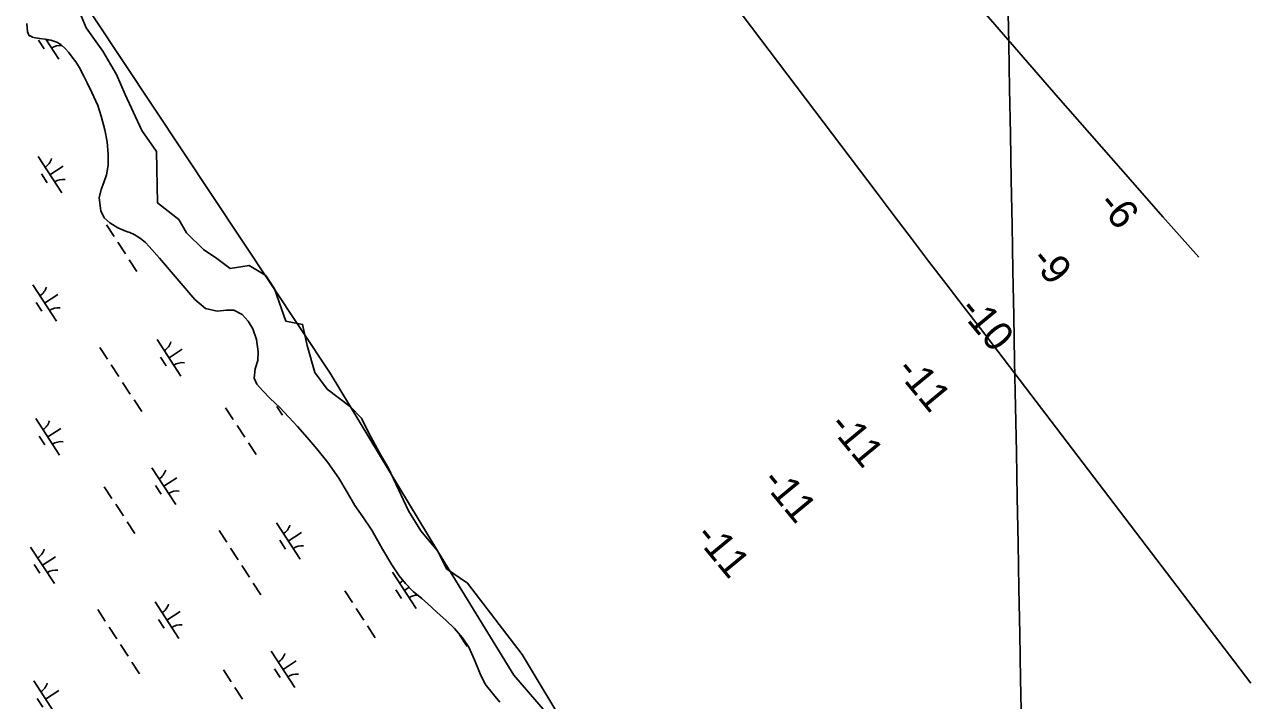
# Model space of a CAD drawing. Extents: x 3953924 to 3974542, y 193747 to 216192.
# Drawn here: x 3966813 to 3968214, y 199028 to 199804 of the extents above; entities that cross this region are included whole.
import ezdxf

# ---------------------------------------------------------------- set-up
doc = ezdxf.new("R2010")
doc.units = 0
for name, color, linetype in [('V-GRID-MAJR', 7, 'Continuous'), ('V-RIVR-EDGE', 7, 'Continuous'), ('V-RIVR-JETY', 7, 'Continuous'), ('V-RIVR-RANG', 7, 'Continuous'), ('V-TOPO-MINR', 7, 'Continuous'), ('V-WETL-SWMP', 7, 'Continuous')]:
    doc.layers.add(name, color=color, linetype=linetype)

msp = doc.modelspace()

# ---------------------------------------------------------------- linework, layer by layer
at = {"layer": 'V-GRID-MAJR'}
msp.add_spline([(3967994.9, 197070.8), (3967932.3, 200408.2), (3967818.6, 206468.2), (3967751, 210066.7)], degree=3, dxfattribs=at)
at = {"layer": 'V-RIVR-EDGE'}
msp.add_lwpolyline([(3966869.1, 199837.6), (3966884.5, 199800.5), (3966903.7, 199773.6), (3966919.1, 199746.7), (3966929.3, 199723.7), (3966948.5, 199682.7), (3966965.2, 199658.4), (3966966.5, 199599.4), (3966990.8, 199580.2), (3966999.8, 199564.9), (3967019, 199545.7), (3967034.3, 199535.4), (3967049.7, 199523.9), (3967071.5, 199527.7), (3967090.7, 199516.2), (3967100.9, 199500.8), (3967113.7, 199463.7), (3967132.9, 199459.9), (3967138.1, 199435.5), (3967147, 199404.8), (3967161.1, 199385.6), (3967188, 199365.1), (3967200.8, 199352.3), (3967208.5, 199335.6), (3967221.3, 199312.6), (3967231.5, 199294.7), (3967254.6, 199246), (3967268.7, 199222.9), (3967287.9, 199199.9), (3967298.1, 199179.4), (3967322.5, 199162.7), (3967385.2, 199080.8), (3967437.7, 198993.7)], dxfattribs=at)
at = {"layer": 'V-RIVR-JETY'}
msp.add_lwpolyline([(3965387.4, 201766), (3965676.4, 201395.8), (3965795.6, 201267.6), (3965922, 201152), (3966044.8, 201002.1), (3966216.4, 200738.4), (3966283.2, 200639.1), (3966436.7, 200467.6), (3966530.6, 200361), (3966624.5, 200225.5), (3966685.9, 200111.8), (3966696.8, 200091.9), (3966718.4, 200064.8), (3966859.3, 199862.5), (3966893.6, 199812), (3967164.5, 199403.8), (3967289.1, 199197.9), (3967375.8, 199057.1), (3967522.1, 198887.3), (3967612.4, 198786.2), (3967746, 198636.3), (3967827.3, 198542.4), (3968004.3, 198338.3), (3968150.6, 198174)], dxfattribs=at)
at = {"layer": 'V-TOPO-MINR'}
for points in [[(3968162.6, 199537.2), (3968121.1, 199583.5), (3968086.5, 199622.8), (3968000.8, 199720.6), (3967915.6, 199818.9), (3967831, 199917.8), (3967746.9, 200017.1), (3967610.1, 200179.9), (3967594.8, 200198.2), (3967579.6, 200216.4), (3967564.4, 200234.8), (3967549.3, 200253.1), (3967127.4, 200767.1)], [(3968222.1, 199047.8), (3967951.2, 199403.4), (3967931.4, 199429.3), (3967911.6, 199455.1), (3967891.8, 199481), (3967872, 199506.8), (3967852.1, 199532.6), (3967832.3, 199558.5), (3967812.6, 199584.4), (3967792.9, 199610.4), (3967452.8, 200059.9)]]:
    msp.add_lwpolyline(points, dxfattribs=at)
at = {"layer": 'V-WETL-SWMP'}
for p, q in [((3966816.3, 199805.2), (3966816.9, 199795.9)), ((3966816.9, 199795.9), (3966819.1, 199791.2)), ((3966819.1, 199791.2), (3966819.9, 199791.2)), ((3966819.9, 199791.2), (3966822.6, 199789.6)), ((3966822.6, 199789.6), (3966826.1, 199789.1)), ((3966826.1, 199789.1), (3966830.7, 199788.3)), ((3966829.5, 199786.3), (3966836, 199776.2)), ((3966830.7, 199788.3), (3966837.3, 199787.4)), ((3966837.3, 199787.4), (3966843.9, 199786.1)), ((3966838.1, 199787.2), (3966852.9, 199764.5)), ((3966839.2, 199785.5), (3966841, 199786.6)), ((3966843.9, 199786.1), (3966850.5, 199784)), ((3966850.5, 199784), (3966855.1, 199781.2)), ((3966855.1, 199781.2), (3966860.8, 199776.4)), ((3966860.8, 199776.4), (3966864.2, 199772.4)), ((3966864.2, 199772.4), (3966868.4, 199766.9)), ((3966868.4, 199766.9), (3966872.6, 199761.4)), ((3966872.6, 199761.4), (3966876.3, 199755.1)), ((3966876.3, 199755.1), (3966881.6, 199744.9)), ((3966881.6, 199744.9), (3966885.7, 199737.1)), ((3966885.7, 199737.1), (3966890.9, 199726.1)), ((3966890.9, 199726.1), (3966897.6, 199711.2)), ((3966897.6, 199711.2), (3966901.7, 199699)), ((3966901.7, 199699), (3966906, 199683.4)), ((3966906, 199683.4), (3966908.5, 199669.4)), ((3966908.5, 199669.4), (3966909.8, 199655)), ((3966909.8, 199655), (3966909.5, 199642.9)), ((3966829.1, 199652.7), (3966856.3, 199610.8)), ((3966842.7, 199631.8), (3966857.8, 199641.6)), ((3966909.5, 199642.9), (3966907.8, 199631.7)), ((3966833, 199632.6), (3966839.5, 199622.5)), ((3966907.8, 199631.7), (3966904.5, 199622.8)), ((3966901.6, 199614.7), (3966899.5, 199605.4)), ((3966904.5, 199622.8), (3966901.6, 199614.7)), ((3966899.5, 199605.4), (3966901.1, 199590.2)), ((3966901.1, 199590.2), (3966904.9, 199582.4)), ((3966904.9, 199582.4), (3966911.4, 199576.4)), ((3966907.7, 199574.4), (3966916.5, 199561)), ((3966911.4, 199576.4), (3966920.6, 199570.8)), ((3966920.6, 199570.8), (3966930.6, 199566.7)), ((3966930.6, 199566.7), (3966934.5, 199565.5)), ((3966934.5, 199565.5), (3966939.5, 199563.1)), ((3966939.5, 199563.1), (3966946.8, 199558.6)), ((3966946.8, 199558.6), (3966952.5, 199553.9)), ((3966920.8, 199554.3), (3966929.5, 199540.9)), ((3966952.5, 199553.9), (3966956.7, 199549.5)), ((3966956.7, 199549.5), (3966968.5, 199536.1)), ((3966933.9, 199534.2), (3966942.6, 199520.8)), ((3966968.5, 199536.1), (3967009.1, 199488.6)), ((3966823.1, 199505.4), (3966850.4, 199463.5)), ((3966836.7, 199484.4), (3966851.8, 199494.2)), ((3967009.1, 199488.6), (3967021.4, 199478.3)), ((3966827, 199485.2), (3966833.5, 199475.2)), ((3967021.4, 199478.3), (3967034.9, 199474.9)), ((3967034.9, 199474.9), (3967045.4, 199476.3)), ((3967045.4, 199476.3), (3967054, 199476.1)), ((3967054, 199476.1), (3967063.6, 199471.3)), ((3967063.6, 199471.3), (3967070.5, 199463.7)), ((3967070.5, 199463.7), (3967075.7, 199454.7)), ((3967075.7, 199454.7), (3967080.2, 199442.6)), ((3966900.1, 199433.5), (3966908.9, 199420.1)), ((3966966, 199442.4), (3966993.2, 199400.5)), ((3966979.6, 199421.5), (3966994.7, 199431.3)), ((3967080.2, 199442.6), (3967081.8, 199428.2)), ((3966969.9, 199422.3), (3966976.4, 199412.2)), ((3967081.6, 199418.4), (3967078.7, 199408.8)), ((3967081.8, 199428.2), (3967081.6, 199418.4)), ((3966913.2, 199413.4), (3966922, 199400)), ((3967078.7, 199408.8), (3967077.4, 199398.3)), ((3966926.3, 199393.3), (3966935.1, 199379.8)), ((3967077.4, 199398.3), (3967080.3, 199391.3)), ((3967080.3, 199391.3), (3967086.8, 199384.1)), ((3967086.8, 199384.1), (3967095.9, 199375)), ((3967095.9, 199375), (3967107, 199364.3)), ((3966939.4, 199373.1), (3966948.2, 199359.7)), ((3967044.6, 199364.1), (3967053.4, 199350.7)), ((3967103.3, 199365.7), (3967109.8, 199355.6)), ((3967107, 199364.3), (3967117.3, 199353.2)), ((3966826.6, 199351.7), (3966853.8, 199309.8)), ((3967117.3, 199353.2), (3967127.2, 199342.6)), ((3966840.2, 199330.7), (3966855.3, 199340.5)), ((3967057.7, 199344), (3967066.5, 199330.6)), ((3967127.2, 199342.6), (3967138.2, 199329.9)), ((3966830.5, 199331.5), (3966837, 199321.5)), ((3967070.8, 199323.9), (3967079.5, 199310.5)), ((3967138.2, 199329.9), (3967149.2, 199316.9)), ((3967149.2, 199316.9), (3967161.8, 199301.5)), ((3966960, 199295.1), (3966987.3, 199253.1)), ((3967161.8, 199301.5), (3967174.6, 199283.3)), ((3966973.6, 199274.1), (3966988.7, 199283.9)), ((3967174.6, 199283.3), (3967184, 199267.2)), ((3966905.2, 199273.4), (3966914, 199260)), ((3966963.9, 199274.9), (3966970.4, 199264.9)), ((3967184, 199267.2), (3967193.1, 199251.9)), ((3966918.3, 199253.3), (3966927.1, 199239.9)), ((3967193.1, 199251.9), (3967202.1, 199238.9)), ((3967202.1, 199238.9), (3967212.7, 199223.5)), ((3966931.4, 199233.1), (3966940.1, 199219.7)), ((3967037.1, 199223.2), (3967045.8, 199209.8)), ((3967102.9, 199232.1), (3967130.2, 199190.2)), ((3967116.5, 199211.1), (3967131.6, 199221)), ((3967212.7, 199223.5), (3967224.7, 199201.9)), ((3967106.8, 199212), (3967113.3, 199201.9)), ((3966820.6, 199204.3), (3966847.9, 199162.4)), ((3966834.2, 199183.4), (3966849.3, 199193.2)), ((3967050.1, 199203), (3967058.9, 199189.6)), ((3967224.7, 199201.9), (3967235.6, 199183.8)), ((3966824.5, 199184.2), (3966831, 199174.1)), ((3967063.2, 199182.9), (3967072, 199169.5)), ((3967235.6, 199183.8), (3967244, 199171.2)), ((3967236.3, 199175.5), (3967263.6, 199133.6)), ((3967244, 199171.2), (3967251.2, 199162.5)), ((3967076.3, 199162.8), (3967085.1, 199149.4)), ((3967181.5, 199153.8), (3967190.3, 199140.4)), ((3967240.2, 199155.3), (3967246.7, 199145.3)), ((3967249.9, 199154.5), (3967255.4, 199158.1)), ((3967251.2, 199162.5), (3967259.9, 199153.4)), ((3967259.9, 199153.4), (3967269.9, 199145.1)), ((3966963.5, 199141.3), (3966990.7, 199099.4)), ((3967269.9, 199145.1), (3967276.4, 199139.5)), ((3967276.4, 199139.5), (3967287.4, 199129.2)), ((3966897.7, 199132.4), (3966906.4, 199119)), ((3966977.1, 199120.4), (3966992.2, 199130.2)), ((3967194.6, 199133.7), (3967203.4, 199120.3)), ((3967287.4, 199129.2), (3967297.4, 199120.4)), ((3966910.7, 199112.3), (3966919.5, 199098.9)), ((3966967.4, 199121.2), (3966973.9, 199111.2)), ((3967207.7, 199113.6), (3967216.5, 199100.2)), ((3967297.4, 199120.4), (3967307.3, 199110.9)), ((3967307.3, 199110.9), (3967316.8, 199100.2)), ((3967313.4, 199103.6), (3967322.1, 199090.2)), ((3967316.8, 199100.2), (3967324, 199089.2)), ((3966923.8, 199092.2), (3966932.6, 199078.8)), ((3967096.9, 199084.7), (3967124.2, 199042.8)), ((3967324, 199089.2), (3967330.3, 199074.7)), ((3967326.5, 199083.5), (3967326.6, 199083.3)), ((3966936.9, 199072.1), (3966945.7, 199058.7)), ((3967110.5, 199063.8), (3967125.6, 199073.6)), ((3967330.3, 199074.7), (3967337, 199058.7)), ((3967042.1, 199063.1), (3967050.9, 199049.6)), ((3967100.8, 199064.6), (3967107.3, 199054.5)), ((3967337, 199058.7), (3967342.6, 199046.9)), ((3966824.1, 199050.6), (3966851.3, 199008.7)), ((3966837.7, 199029.7), (3966852.8, 199039.5)), ((3967055.2, 199042.9), (3967064, 199029.5)), ((3967342.6, 199046.9), (3967352.1, 199035)), ((3966828, 199030.5), (3966834.5, 199020.4)), ((3967352.1, 199035), (3967359.7, 199026.3))]:
    msp.add_line(p, q, dxfattribs=at)
for centre, start, end in [((3966854.5, 199762.5), 83.3317, 123.8337), ((3966827.8, 199655.1), 302.2901, 343.8338), ((3966858, 199608.8), 82.2901, 123.8337), ((3966821.8, 199507.7), 302.2901, 343.8338), ((3966852, 199461.4), 82.2901, 123.8337), ((3966964.7, 199444.7), 302.2901, 343.8338), ((3966994.9, 199398.4), 82.2901, 123.8337), ((3966825.3, 199354), 302.2901, 343.8338), ((3966855.5, 199307.7), 82.2901, 123.8337), ((3966958.8, 199297.4), 302.2901, 343.8338), ((3966988.9, 199251.1), 82.2901, 123.8337), ((3967101.6, 199234.4), 302.2901, 343.8338), ((3967131.8, 199188.1), 82.2901, 123.8337), ((3966819.3, 199206.6), 302.2901, 343.8338), ((3966849.5, 199160.3), 82.2901, 123.8337), ((3967235.1, 199177.8), 302.2901, 318.3184), ((3966962.2, 199143.7), 302.2901, 343.8338), ((3967265.2, 199131.5), 90.4889, 123.8337), ((3966992.4, 199097.4), 82.2901, 123.8337), ((3967095.7, 199087.1), 302.2901, 343.8338), ((3967125.8, 199040.8), 82.2901, 123.8337), ((3966822.8, 199052.9), 302.2901, 343.8338)]:
    msp.add_arc(centre, 17.6, start, end, dxfattribs=at)

# ---------------------------------------------------------------- texts
at = {"layer": 'V-RIVR-RANG'}
for s, p in [('-6', (3968045, 199597.3)), ('-9', (3967967.9, 199533.5)), ('-10', (3967885.6, 199476.1)), ('-11', (3967813.2, 199406.7)), ('-11', (3967736.1, 199343)), ('-11', (3967659, 199279.3)), ('-11', (3967582.3, 199216))]:
    msp.add_text(s, height=33.5, rotation=309.5554, dxfattribs=at).set_placement(p)

doc.saveas('drawing.dxf')
